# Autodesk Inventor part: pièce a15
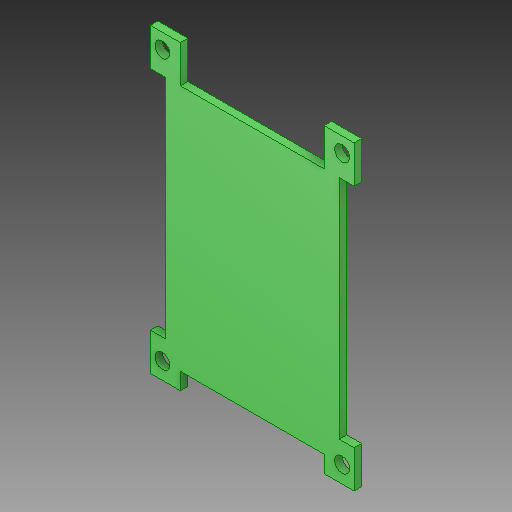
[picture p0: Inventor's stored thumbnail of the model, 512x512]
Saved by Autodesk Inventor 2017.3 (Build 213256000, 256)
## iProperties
Created: 2007-12
Part Number: pièce a15
Material: solidworks materials|PVC 0.007 plastifié|45
Document SubType Name: Modeling
Designer: ficho
Appearance: 0,192,0
Author: ficho
Sending System: SolidWorks 2009
Last Author: christophe
Last Saved: 2011-02-10
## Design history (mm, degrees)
feature "Enlèv. mat.-Extru.1"
node "Solide1"
